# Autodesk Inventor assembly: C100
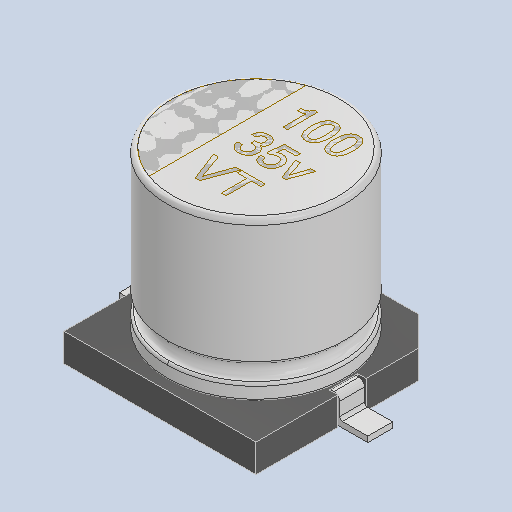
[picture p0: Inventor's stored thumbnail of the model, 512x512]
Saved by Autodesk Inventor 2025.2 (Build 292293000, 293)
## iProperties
Created: 2025-04
Part Number: C100
Description: PART--DESC
Document SubType Name: Assembly
Designer: BennF
Author: BennF
Revision Number: NONE
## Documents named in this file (4)
- C:\Users\BennF\Nextcloud\Benutzer\CNC JarBeRi\existing parts\Electronics\RepRap A4988 Shied (USE WITHOUT ARDUINO)\reprap-a4988-1.snapshot.1\RepRap\RepRap\C100_3.iam
- C:\Users\BennF\Nextcloud\Benutzer\CNC JarBeRi\existing parts\Electronics\RepRap A4988 Shied (USE WITHOUT ARDUINO)\reprap-a4988-1.snapshot.1\RepRap\RepRap\C100 Geometry.ipt
- C:\Users\BennF\Nextcloud\Benutzer\CNC JarBeRi\existing parts\Electronics\RepRap A4988 Shied (USE WITHOUT ARDUINO)\reprap-a4988-1.snapshot.1\RepRap\RepRap\name3.ipt
- C:\Users\BennF\Nextcloud\Benutzer\CNC JarBeRi\existing parts\Electronics\RepRap A4988 Shied (USE WITHOUT ARDUINO)\reprap-a4988-1.snapshot.1\RepRap\RepRap\bay_3.iam
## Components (3 placed, 3 different names)
1. C100 Geometry
2. name3
3. bay [sub-assembly]
